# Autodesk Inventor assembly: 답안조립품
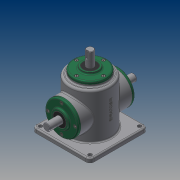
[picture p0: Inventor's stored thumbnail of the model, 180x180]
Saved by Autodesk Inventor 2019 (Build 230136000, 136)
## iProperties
Created: 2019-03
Part Number: 답안조립품
Material: 일반
Document SubType Name: Assembly
Designer: PC312-09
Author: PC312-09
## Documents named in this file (16)
- C:\Users\PC312-09\Desktop\490314V1009\답안조립품.iam
- C:\Users\PC312-09\Desktop\490314V1009\본체.ipt
- C:\Users\PC312-09\Desktop\490314V1009\커버.ipt
- C:\Users\PC312-09\Desktop\490314V1009\베어링 6203.ipt
- C:\Users\PC312-09\Desktop\490314V1009\메인 축.ipt
- 메인 축.ipt
- C:\Users\PC312-09\Desktop\490314V1009\서브 축.ipt
- 서브 축.ipt
- C:\Users\PC312-09\Desktop\490314V1009\오일 실.ipt
- 오일 실.ipt
- C:\Users\PC312-09\Desktop\490314V1009\키 5x5.ipt
- C:\Users\PC312-09\Desktop\490314V1009\키 4x4.ipt
- C:\Users\PC312-09\Desktop\490314V1009\메인 베벨기어.ipt
- C:\Users\PC312-09\Desktop\490314V1009\서브 베벨기어.ipt
- C:\Users\PC312-09\Desktop\490314V1009\볼트 M4.ipt
- 볼트 M4.ipt
